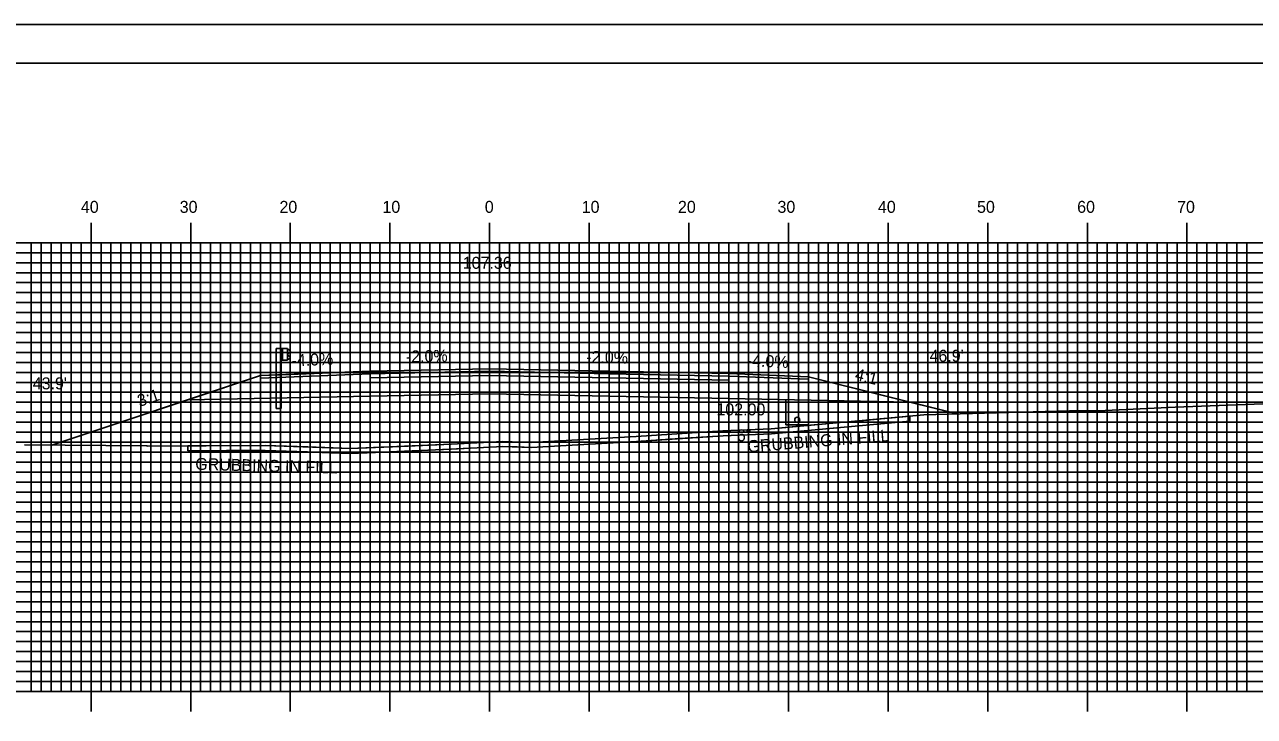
# Model space of a CAD drawing. Extents: x 1755495 to 1755838, y 442591 to 442811.
# Drawn here: x 1755613.9 to 1755737.3, y 442741.2 to 442810.5 of the extents above; entities that cross this region are included whole.
import ezdxf

# ---------------------------------------------------------------- set-up
doc = ezdxf.new("R2010")
doc.units = 0
for name, color, linetype in [('ANNOTATION', 7, 'Continuous'), ('BORDER', 7, 'Continuous'), ('D_Guardrail_Beam_Lt', 7, 'Continuous'), ('D_Roadway_Centerline', 7, 'Continuous'), ('D_Roadway_Centerline_Text', 7, 'Continuous'), ('D_Roadway_Edge_Shoulder', 7, 'Continuous'), ('D_Roadway_Edge_TW', 7, 'Continuous'), ('D_Roadway_Pavement', 7, 'Continuous'), ('D_Roadway_SlopeLines', 7, 'Continuous'), ('D_Roadway_SubGrade', 7, 'Continuous'), ('D_Text_Standard', 7, 'Continuous'), ('GRUBBING IN FILL', 7, 'Continuous'), ('H_V ANNOTATION', 7, 'Continuous'), ('MAJOR', 7, 'Continuous'), ('MINOR', 7, 'Continuous'), ('PDRAIN', 7, 'Continuous'), ('PLOT BOUNDARY', 7, 'Continuous'), ('S_Roadway_Centerline', 7, 'Continuous')]:
    doc.layers.add(name, color=color, linetype=linetype)

msp = doc.modelspace()

# ---------------------------------------------------------------- linework, layer by layer
at = {"layer": 'BORDER'}
msp.add_lwpolyline([(1755510.94, 442596.67), (1755830.94, 442596.67), (1755830.94, 442806.67), (1755510.94, 442806.67)], close=True, dxfattribs=at)
at = {"layer": 'D_Guardrail_Beam_Lt'}
for p, q in [((1755639.11, 442778.05), (1755639.11, 442772.05)), ((1755639.59, 442778.05), (1755639.11, 442778.05)), ((1755640.27, 442778.05), (1755639.59, 442778.05)), ((1755639.59, 442778.05), (1755639.59, 442776.88)), ((1755639.65, 442778.05), (1755639.65, 442776.88)), ((1755639.75, 442778.05), (1755639.75, 442776.88)), ((1755640.27, 442776.88), (1755640.27, 442778.05)), ((1755640.27, 442777.97), (1755640.35, 442777.95)), ((1755640.28, 442777.5), (1755640.28, 442777.43)), ((1755640.51, 442777.7), (1755640.31, 442777.57)), ((1755640.31, 442777.37), (1755640.51, 442777.23)), ((1755640.36, 442777.95), (1755640.51, 442777.85)), ((1755639.59, 442776.88), (1755640.27, 442776.88)), ((1755639.61, 442772.05), (1755639.61, 442776.88)), ((1755640.35, 442776.98), (1755640.27, 442776.97)), ((1755640.51, 442777.09), (1755640.36, 442776.99)), ((1755639.61, 442772.05), (1755639.11, 442772.05))]:
    msp.add_line(p, q, dxfattribs=at)
for centre, major_axis, start_param, end_param in [((1755640.36, 442777.5), (-0.0789, 0), 5.323254, 6.283185), ((1755640.36, 442777.43), (-0.0789, 0), 6.283185, 7.243116), ((1755640.34, 442777.91), (0.0417, 0), 0.959931, 1.376053), ((1755640.46, 442777.78), (0.0877, 0), 5.323254, 7.243116), ((1755640.46, 442777.16), (0.0877, 0), 5.323254, 7.243116), ((1755640.34, 442777.02), (0.0417, 0), 4.907132, 5.323254)]:
    msp.add_ellipse(centre, major_axis=major_axis, ratio=0.995501, start_param=start_param, end_param=end_param, dxfattribs=at)
at = {"layer": 'D_Roadway_Centerline'}
msp.add_lwpolyline([(1755616.62, 442768.37), (1755630.27, 442772.92), (1755637.54, 442775.35), (1755640.54, 442775.47), (1755648.54, 442775.79), (1755660.54, 442776.03), (1755672.54, 442775.79), (1755684.54, 442775.55), (1755692.54, 442775.23), (1755702.72, 442772.68), (1755707.47, 442771.5)], dxfattribs=at)
at = {"layer": 'D_Roadway_Edge_Shoulder'}
for points in [[(1755648.54, 442775.79), (1755640.54, 442775.47), (1755640.54, 442775.47), (1755637.54, 442775.35), (1755637.54, 442775.1), (1755648.54, 442775.54)], [(1755648.54, 442775.79), (1755637.54, 442775.35), (1755637.54, 442775.1), (1755648.54, 442775.54)], [(1755684.54, 442775.55), (1755692.54, 442775.23), (1755692.54, 442774.98), (1755684.54, 442775.3)]]:
    msp.add_lwpolyline(points, close=True, dxfattribs=at)
at = {"layer": 'D_Roadway_Edge_TW'}
for points in [[(1755648.54, 442775.54), (1755648.54, 442775.79), (1755660.54, 442776.03), (1755672.54, 442775.79), (1755672.54, 442775.54), (1755660.54, 442775.78)], [(1755672.54, 442775.79), (1755684.54, 442775.55), (1755684.54, 442775.3), (1755672.54, 442775.54)]]:
    msp.add_lwpolyline(points, close=True, dxfattribs=at)
at = {"layer": 'D_Roadway_Pavement'}
for points in [[(1755648.54, 442775.12), (1755648.54, 442775.54), (1755660.54, 442775.78), (1755672.54, 442775.54), (1755672.54, 442775.12), (1755660.54, 442775.36)], [(1755672.54, 442775.54), (1755684.54, 442775.3), (1755684.54, 442774.88), (1755672.54, 442775.12)]]:
    msp.add_lwpolyline(points, close=True, dxfattribs=at)
for points in [[(1755648.54, 442775.54), (1755648.54, 442775.12)], [(1755684.54, 442775.3), (1755684.54, 442774.88)], [(1755684.54, 442775.3), (1755684.54, 442774.88)], [(1755684.54, 442775.3), (1755684.54, 442774.88)]]:
    msp.add_lwpolyline(points, dxfattribs=at)
at = {"layer": 'D_Roadway_SlopeLines'}
for points in [[(1755637.54, 442775.35), (1755616.62, 442768.37)], [(1755692.54, 442775.23), (1755707.47, 442771.5)]]:
    msp.add_lwpolyline(points, dxfattribs=at)
at = {"layer": 'D_Roadway_SubGrade'}
for points in [[(1755648.54, 442775.12), (1755648.54, 442775.54), (1755637.54, 442775.1), (1755637.54, 442775.35), (1755630.27, 442772.92), (1755648.54, 442773.29)], [(1755648.54, 442773.29), (1755648.54, 442775.12), (1755660.54, 442775.36), (1755672.54, 442775.12), (1755672.54, 442773.29), (1755660.54, 442773.53)], [(1755672.54, 442775.12), (1755684.54, 442774.88), (1755684.54, 442773.05), (1755672.54, 442773.29)], [(1755684.54, 442774.88), (1755684.54, 442775.3), (1755692.54, 442774.98), (1755692.54, 442775.23), (1755702.72, 442772.68), (1755684.54, 442773.05)]]:
    msp.add_lwpolyline(points, close=True, dxfattribs=at)
at = {"layer": 'GRUBBING IN FILL'}
for p, q in [((1755702.72, 442771.28), (1755702.72, 442770.78)), ((1755630.27, 442768.31), (1755630.27, 442767.81))]:
    msp.add_line(p, q, dxfattribs=at)
msp.add_lwpolyline([(1755630.27, 442768.31), (1755630.27, 442767.81), (1755634.14, 442767.83), (1755638, 442767.85), (1755642.28, 442767.69), (1755646.56, 442767.53), (1755651.63, 442767.74), (1755659.28, 442768.1), (1755661.87, 442768.24), (1755663.3, 442768.2), (1755664.73, 442768.15), (1755670, 442768.45), (1755675.28, 442768.75), (1755679.63, 442769.04), (1755683.99, 442769.32), (1755688.85, 442769.51), (1755695.78, 442770.15), (1755702.72, 442770.78), (1755702.72, 442771.28), (1755697.01, 442770.76), (1755696.46, 442770.71), (1755690.92, 442770.2), (1755688.81, 442770.01), (1755683.96, 442769.82), (1755675.25, 442769.25), (1755669.98, 442768.95), (1755664.72, 442768.65), (1755661.87, 442768.74), (1755656.67, 442768.46), (1755651.62, 442768.24), (1755646.56, 442768.03), (1755642.29, 442768.19), (1755638.01, 442768.35), (1755632.11, 442768.32), (1755630.5, 442768.31)], close=True, dxfattribs=at)
msp.add_lwpolyline([(1755630.27, 442768.31), (1755630.27, 442767.81), (1755634.14, 442767.83), (1755638, 442767.85), (1755642.28, 442767.69), (1755646.56, 442767.53), (1755651.63, 442767.74), (1755659.28, 442768.1), (1755661.87, 442768.24), (1755663.3, 442768.2), (1755664.73, 442768.15), (1755670, 442768.45), (1755675.28, 442768.75), (1755679.63, 442769.04), (1755683.99, 442769.32), (1755688.85, 442769.51), (1755695.78, 442770.15), (1755702.72, 442770.78), (1755702.72, 442771.28), (1755697.01, 442770.76), (1755696.46, 442770.71), (1755690.92, 442770.2), (1755688.81, 442770.01), (1755683.96, 442769.82), (1755675.25, 442769.25), (1755669.98, 442768.95), (1755664.72, 442768.65), (1755661.87, 442768.74), (1755656.67, 442768.46), (1755651.62, 442768.24), (1755646.56, 442768.03), (1755642.29, 442768.19), (1755638.01, 442768.35), (1755632.11, 442768.32), (1755630.5, 442768.31)], close=True, dxfattribs=at)
msp.add_lwpolyline([(1755630.27, 442767.81), (1755638, 442767.85), (1755646.56, 442767.53), (1755656.69, 442767.96), (1755661.87, 442768.24), (1755664.73, 442768.15), (1755675.28, 442768.75), (1755683.99, 442769.32), (1755688.85, 442769.51), (1755702.72, 442770.78)], dxfattribs=at)
at = {"layer": 'MAJOR'}
for p, q in [((1755620.54, 442790.67), (1755620.54, 442788.67)), ((1755630.54, 442790.67), (1755630.54, 442788.67)), ((1755640.54, 442790.67), (1755640.54, 442788.67)), ((1755650.54, 442790.67), (1755650.54, 442788.67)), ((1755660.54, 442790.67), (1755660.54, 442788.67)), ((1755670.54, 442790.67), (1755670.54, 442788.67)), ((1755680.54, 442790.67), (1755680.54, 442788.67)), ((1755690.54, 442790.67), (1755690.54, 442788.67)), ((1755700.54, 442790.67), (1755700.54, 442788.67)), ((1755710.54, 442790.67), (1755710.54, 442788.67)), ((1755720.54, 442790.67), (1755720.54, 442788.67)), ((1755730.54, 442790.67), (1755730.54, 442788.67)), ((1755520.54, 442788.67), (1755800.54, 442788.67)), ((1755520.54, 442788.67), (1755800.54, 442788.67)), ((1755620.54, 442743.67), (1755620.54, 442788.67)), ((1755630.54, 442743.67), (1755630.54, 442788.67)), ((1755640.54, 442743.67), (1755640.54, 442788.67)), ((1755650.54, 442743.67), (1755650.54, 442788.67)), ((1755660.54, 442743.67), (1755660.54, 442788.67)), ((1755670.54, 442743.67), (1755670.54, 442788.67)), ((1755680.54, 442743.67), (1755680.54, 442788.67)), ((1755690.54, 442743.67), (1755690.54, 442788.67)), ((1755700.54, 442743.67), (1755700.54, 442788.67)), ((1755710.54, 442743.67), (1755710.54, 442788.67)), ((1755720.54, 442743.67), (1755720.54, 442788.67)), ((1755730.54, 442743.67), (1755730.54, 442788.67)), ((1755520.54, 442783.67), (1755800.54, 442783.67)), ((1755520.54, 442778.67), (1755800.54, 442778.67)), ((1755520.54, 442773.67), (1755800.54, 442773.67)), ((1755520.54, 442768.67), (1755800.54, 442768.67)), ((1755520.54, 442763.67), (1755800.54, 442763.67)), ((1755520.54, 442758.67), (1755800.54, 442758.67)), ((1755520.54, 442753.67), (1755800.54, 442753.67)), ((1755520.54, 442748.67), (1755800.54, 442748.67)), ((1755520.54, 442743.67), (1755800.54, 442743.67)), ((1755520.54, 442743.67), (1755800.54, 442743.67)), ((1755620.54, 442741.66), (1755620.54, 442743.67)), ((1755630.54, 442741.66), (1755630.54, 442743.67)), ((1755640.54, 442741.66), (1755640.54, 442743.67)), ((1755650.54, 442741.66), (1755650.54, 442743.67)), ((1755660.54, 442741.66), (1755660.54, 442743.67)), ((1755670.54, 442741.66), (1755670.54, 442743.67)), ((1755680.54, 442741.66), (1755680.54, 442743.67)), ((1755690.54, 442741.66), (1755690.54, 442743.67)), ((1755700.54, 442741.66), (1755700.54, 442743.67)), ((1755710.54, 442741.66), (1755710.54, 442743.67)), ((1755720.54, 442741.66), (1755720.54, 442743.67)), ((1755730.54, 442741.66), (1755730.54, 442743.67))]:
    msp.add_line(p, q, dxfattribs=at)
at = {"layer": 'MINOR'}
for p, q in [((1755614.54, 442743.67), (1755614.54, 442788.67)), ((1755615.54, 442743.67), (1755615.54, 442788.67)), ((1755616.54, 442743.67), (1755616.54, 442788.67)), ((1755617.54, 442743.67), (1755617.54, 442788.67)), ((1755618.54, 442743.67), (1755618.54, 442788.67)), ((1755619.54, 442743.67), (1755619.54, 442788.67)), ((1755621.54, 442743.67), (1755621.54, 442788.67)), ((1755622.54, 442743.67), (1755622.54, 442788.67)), ((1755623.54, 442743.67), (1755623.54, 442788.67)), ((1755624.54, 442743.67), (1755624.54, 442788.67)), ((1755625.54, 442743.67), (1755625.54, 442788.67)), ((1755626.54, 442743.67), (1755626.54, 442788.67)), ((1755627.54, 442743.67), (1755627.54, 442788.67)), ((1755628.54, 442743.67), (1755628.54, 442788.67)), ((1755629.54, 442743.67), (1755629.54, 442788.67)), ((1755631.54, 442743.67), (1755631.54, 442788.67)), ((1755632.54, 442743.67), (1755632.54, 442788.67)), ((1755633.54, 442743.67), (1755633.54, 442788.67)), ((1755634.54, 442743.67), (1755634.54, 442788.67)), ((1755635.54, 442743.67), (1755635.54, 442788.67)), ((1755636.54, 442743.67), (1755636.54, 442788.67)), ((1755637.54, 442743.67), (1755637.54, 442788.67)), ((1755638.54, 442743.67), (1755638.54, 442788.67)), ((1755639.54, 442743.67), (1755639.54, 442788.67)), ((1755641.54, 442743.67), (1755641.54, 442788.67)), ((1755642.54, 442743.67), (1755642.54, 442788.67)), ((1755643.54, 442743.67), (1755643.54, 442788.67)), ((1755644.54, 442743.67), (1755644.54, 442788.67)), ((1755645.54, 442743.67), (1755645.54, 442788.67)), ((1755646.54, 442743.67), (1755646.54, 442788.67)), ((1755647.54, 442743.67), (1755647.54, 442788.67)), ((1755648.54, 442743.67), (1755648.54, 442788.67)), ((1755649.54, 442743.67), (1755649.54, 442788.67)), ((1755651.54, 442743.67), (1755651.54, 442788.67)), ((1755652.54, 442743.67), (1755652.54, 442788.67)), ((1755653.54, 442743.67), (1755653.54, 442788.67)), ((1755654.54, 442743.67), (1755654.54, 442788.67)), ((1755655.54, 442743.67), (1755655.54, 442788.67)), ((1755656.54, 442743.67), (1755656.54, 442788.67)), ((1755657.54, 442743.67), (1755657.54, 442788.67)), ((1755658.54, 442743.67), (1755658.54, 442788.67)), ((1755659.54, 442743.67), (1755659.54, 442788.67)), ((1755661.54, 442743.67), (1755661.54, 442788.67)), ((1755662.54, 442743.67), (1755662.54, 442788.67)), ((1755663.54, 442743.67), (1755663.54, 442788.67)), ((1755664.54, 442743.67), (1755664.54, 442788.67)), ((1755665.54, 442743.67), (1755665.54, 442788.67)), ((1755666.54, 442743.67), (1755666.54, 442788.67)), ((1755667.54, 442743.67), (1755667.54, 442788.67)), ((1755668.54, 442743.67), (1755668.54, 442788.67)), ((1755669.54, 442743.67), (1755669.54, 442788.67)), ((1755671.54, 442743.67), (1755671.54, 442788.67)), ((1755672.54, 442743.67), (1755672.54, 442788.67)), ((1755673.54, 442743.67), (1755673.54, 442788.67)), ((1755674.54, 442743.67), (1755674.54, 442788.67)), ((1755675.54, 442743.67), (1755675.54, 442788.67)), ((1755676.54, 442743.67), (1755676.54, 442788.67)), ((1755677.54, 442743.67), (1755677.54, 442788.67)), ((1755678.54, 442743.67), (1755678.54, 442788.67)), ((1755679.54, 442743.67), (1755679.54, 442788.67)), ((1755681.54, 442743.67), (1755681.54, 442788.67)), ((1755682.54, 442743.67), (1755682.54, 442788.67)), ((1755683.54, 442743.67), (1755683.54, 442788.67)), ((1755684.54, 442743.67), (1755684.54, 442788.67)), ((1755685.54, 442743.67), (1755685.54, 442788.67)), ((1755686.54, 442743.67), (1755686.54, 442788.67)), ((1755687.54, 442743.67), (1755687.54, 442788.67)), ((1755688.54, 442743.67), (1755688.54, 442788.67)), ((1755689.54, 442743.67), (1755689.54, 442788.67)), ((1755691.54, 442743.67), (1755691.54, 442788.67)), ((1755692.54, 442743.67), (1755692.54, 442788.67)), ((1755693.54, 442743.67), (1755693.54, 442788.67)), ((1755694.54, 442743.67), (1755694.54, 442788.67)), ((1755695.54, 442743.67), (1755695.54, 442788.67)), ((1755696.54, 442743.67), (1755696.54, 442788.67)), ((1755697.54, 442743.67), (1755697.54, 442788.67)), ((1755698.54, 442743.67), (1755698.54, 442788.67)), ((1755699.54, 442743.67), (1755699.54, 442788.67)), ((1755701.54, 442743.67), (1755701.54, 442788.67)), ((1755702.54, 442743.67), (1755702.54, 442788.67)), ((1755703.54, 442743.67), (1755703.54, 442788.67)), ((1755704.54, 442743.67), (1755704.54, 442788.67)), ((1755705.54, 442743.67), (1755705.54, 442788.67)), ((1755706.54, 442743.67), (1755706.54, 442788.67)), ((1755707.54, 442743.67), (1755707.54, 442788.67)), ((1755708.54, 442743.67), (1755708.54, 442788.67)), ((1755709.54, 442743.67), (1755709.54, 442788.67)), ((1755711.54, 442743.67), (1755711.54, 442788.67)), ((1755712.54, 442743.67), (1755712.54, 442788.67)), ((1755713.54, 442743.67), (1755713.54, 442788.67)), ((1755714.54, 442743.67), (1755714.54, 442788.67)), ((1755715.54, 442743.67), (1755715.54, 442788.67)), ((1755716.54, 442743.67), (1755716.54, 442788.67)), ((1755717.54, 442743.67), (1755717.54, 442788.67)), ((1755718.54, 442743.67), (1755718.54, 442788.67)), ((1755719.54, 442743.67), (1755719.54, 442788.67)), ((1755721.54, 442743.67), (1755721.54, 442788.67)), ((1755722.54, 442743.67), (1755722.54, 442788.67)), ((1755723.54, 442743.67), (1755723.54, 442788.67)), ((1755724.54, 442743.67), (1755724.54, 442788.67)), ((1755725.54, 442743.67), (1755725.54, 442788.67)), ((1755726.54, 442743.67), (1755726.54, 442788.67)), ((1755727.54, 442743.67), (1755727.54, 442788.67)), ((1755728.54, 442743.67), (1755728.54, 442788.67)), ((1755729.54, 442743.67), (1755729.54, 442788.67)), ((1755731.54, 442743.67), (1755731.54, 442788.67)), ((1755732.54, 442743.67), (1755732.54, 442788.67)), ((1755733.54, 442743.67), (1755733.54, 442788.67)), ((1755734.54, 442743.67), (1755734.54, 442788.67)), ((1755735.54, 442743.67), (1755735.54, 442788.67)), ((1755736.54, 442743.67), (1755736.54, 442788.67)), ((1755520.54, 442787.67), (1755800.54, 442787.67)), ((1755520.54, 442786.67), (1755800.54, 442786.67)), ((1755520.54, 442785.67), (1755800.54, 442785.67)), ((1755520.54, 442784.67), (1755800.54, 442784.67)), ((1755520.54, 442782.67), (1755800.54, 442782.67)), ((1755520.54, 442781.67), (1755800.54, 442781.67)), ((1755520.54, 442780.67), (1755800.54, 442780.67)), ((1755520.54, 442779.67), (1755800.54, 442779.67)), ((1755520.54, 442777.67), (1755800.54, 442777.67)), ((1755520.54, 442776.67), (1755800.54, 442776.67)), ((1755520.54, 442775.67), (1755800.54, 442775.67)), ((1755520.54, 442774.67), (1755800.54, 442774.67)), ((1755520.54, 442772.67), (1755800.54, 442772.67)), ((1755520.54, 442771.67), (1755800.54, 442771.67)), ((1755520.54, 442770.67), (1755800.54, 442770.67)), ((1755520.54, 442769.67), (1755800.54, 442769.67)), ((1755520.54, 442767.67), (1755800.54, 442767.67)), ((1755520.54, 442766.67), (1755800.54, 442766.67)), ((1755520.54, 442765.67), (1755800.54, 442765.67)), ((1755520.54, 442764.67), (1755800.54, 442764.67)), ((1755520.54, 442762.67), (1755800.54, 442762.67)), ((1755520.54, 442761.67), (1755800.54, 442761.67)), ((1755520.54, 442760.67), (1755800.54, 442760.67)), ((1755520.54, 442759.67), (1755800.54, 442759.67)), ((1755520.54, 442757.67), (1755800.54, 442757.67)), ((1755520.54, 442756.67), (1755800.54, 442756.67)), ((1755520.54, 442755.67), (1755800.54, 442755.67)), ((1755520.54, 442754.67), (1755800.54, 442754.67)), ((1755520.54, 442752.67), (1755800.54, 442752.67)), ((1755520.54, 442751.67), (1755800.54, 442751.67)), ((1755520.54, 442750.67), (1755800.54, 442750.67)), ((1755520.54, 442749.67), (1755800.54, 442749.67)), ((1755520.54, 442747.67), (1755800.54, 442747.67)), ((1755520.54, 442746.67), (1755800.54, 442746.67)), ((1755520.54, 442745.67), (1755800.54, 442745.67)), ((1755520.54, 442744.67), (1755800.54, 442744.67))]:
    msp.add_line(p, q, dxfattribs=at)
at = {"layer": 'PDRAIN'}
msp.add_line((1755682.7, 442770.67), (1755691.42, 442770.67), dxfattribs=at)
msp.add_lwpolyline([(1755690.29, 442772.93), (1755690.29, 442770.42), (1755692.54, 442770.42), (1755692.54, 442772.89)], dxfattribs=at)
msp.add_circle((1755691.42, 442770.92), 0.25, dxfattribs=at)
at = {"layer": 'PLOT BOUNDARY'}
msp.add_lwpolyline([(1755494.76, 442590.55), (1755834.76, 442590.55), (1755834.76, 442810.55), (1755494.76, 442810.55)], close=True, dxfattribs=at)
at = {"layer": 'S_Roadway_Centerline'}
msp.add_lwpolyline([(1755613.87, 442768.4), (1755626.11, 442768.29), (1755626.17, 442768.29), (1755626.2, 442768.28), (1755638.01, 442768.35), (1755646.56, 442768.03), (1755656.67, 442768.46), (1755661.87, 442768.74), (1755664.72, 442768.65), (1755675.25, 442769.25), (1755683.96, 442769.82), (1755688.81, 442770.01), (1755704.12, 442771.41), (1755718.76, 442771.8), (1755722.34, 442771.84), (1755729.34, 442772.17), (1755742.58, 442772.68)], dxfattribs=at)

# ---------------------------------------------------------------- texts
at = {"layer": 'ANNOTATION'}
for s, rotation, p in [('-4.0%', 2.2906, (1755640.68, 442776.27)), ('-2.0%', 1.1458, (1755652.15, 442776.66)), ('-2.0%', 358.8542, (1755670.23, 442776.63)), ('-4.0%', 357.7094, (1755686.34, 442776.28)), ('4:1', 345.9638, (1755697.14, 442774.94)), ('3:1', 18.4349, (1755625.42, 442772.21))]:
    msp.add_text(s, height=1.2, rotation=rotation, dxfattribs=at).set_placement(p)
for s, p in [('102.00', (1755683.31, 442771.36)), ('6"', (1755685.36, 442768.76))]:
    msp.add_text(s, height=1.2, dxfattribs=at).set_placement(p)
at = {"layer": 'D_Roadway_Centerline'}
for s, p in [('C', (1755660.54, 442776.03)), ('L', (1755660.54, 442776.02))]:
    msp.add_text(s, height=0.0146, dxfattribs=at).set_placement(p)
at = {"layer": 'D_Roadway_Centerline_Text'}
msp.add_text('107.36', height=1.2, dxfattribs=at).set_placement((1755657.85, 442786.06))
at = {"layer": 'D_Text_Standard'}
for s, p in [("46.9'", (1755704.7, 442776.74)), ("43.9'", (1755614.69, 442773.97))]:
    msp.add_text(s, height=1.2, dxfattribs=at).set_placement(p)
at = {"layer": 'GRUBBING IN FILL'}
for rotation, p in [(4.5261, (1755686.48, 442767.64)), (358.498, (1755630.99, 442765.9))]:
    msp.add_text('GRUBBING IN FILL', height=1.2, rotation=rotation, dxfattribs=at).set_placement(p)
at = {"layer": 'H_V ANNOTATION'}
for s, p in [('40', (1755619.52, 442791.67)), ('30', (1755629.44, 442791.67)), ('20', (1755639.45, 442791.67)), ('10', (1755649.79, 442791.67)), ('0', (1755660.06, 442791.67)), ('10', (1755669.79, 442791.67)), ('20', (1755679.45, 442791.67)), ('30', (1755689.44, 442791.67)), ('40', (1755699.52, 442791.67)), ('50', (1755709.47, 442791.67)), ('60', (1755719.52, 442791.67)), ('70', (1755729.55, 442791.67))]:
    msp.add_text(s, height=1.2, dxfattribs=at).set_placement(p)

doc.saveas('drawing.dxf')
